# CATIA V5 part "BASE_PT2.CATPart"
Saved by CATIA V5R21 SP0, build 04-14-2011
Part number: BASE_PT2
Bounding box of the stored display mesh (mm): x -5 to 7, y -45.5 to 45.5, z -21.5 to 21.5
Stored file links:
  D:\MENA 3D\BISMARK\BASE_PT2.CATPart
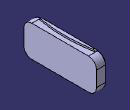
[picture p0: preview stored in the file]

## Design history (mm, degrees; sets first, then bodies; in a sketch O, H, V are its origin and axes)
Body1 (main body)
  Sketch1 on yz-plane, origin (0, 0, 0), H (0, 1, 0), V (0, 0, 1)
    line L1 (45.5, 9.5) -> (45.5, -9.5)
    line L2 (35.5, -19.5) -> (-35.5, -19.5)
    line L3 (-45.5, -9.5) -> (-45.5, 9.5)
    line L4 (-35.5, 19.5) -> (35.5, 19.5)
    arc A1 centre (-35.5, 9.5) radius 10 from (-45.5, 9.5) to (-35.5, 19.5) cw
    arc A2 centre (35.5, 9.5) radius 10 from (45.5, 9.5) to (35.5, 19.5) ccw
    arc A3 centre (-35.5, -9.5) radius 10 from (-35.5, -19.5) to (-45.5, -9.5) cw
    arc A4 centre (35.5, -9.5) radius 10 from (45.5, -9.5) to (35.5, -19.5) cw
    distance L3 L1 = 91
    distance L4 L2 = 39
    radius A1 = 10
    radius A2 = 10
    radius A3 = 10
    radius A4 = 10
    vertical: L1 V, L3 V
    horizontal: L2 H, L4 H
    equidistance: L1 L3 O, L2 L4 O
    tangency: A1 L3, A1 L4, A2 L1, A2 L4, A3 L2, A3 L3, A4 L1, A4 L2
  Pad1: profile Sketch1, direction (1, 0, 0), length 7, opposite side length 5
  Sketch2 on face of Pad1, origin (0, 0, 19.5), H (1, 0, 0), V (0, 1, 0)
    point P1 (-1.75, 35)
    line L1 (-1.75, 35) -> (-5, 35)
    line L2 (-5, 35) -> (-5, -35)
    line L3 (-5, -35) -> (-1.75, -35)
    point P4 (-1.75, -35)
    reference projected line E1 (-5, 35.5) -> (-5, -35.5) from edge [start face of Pad1 | face of Pad1 from Sketch1.L4]
    spline S1 through (-1.75, 35) (1.5, 0) (-1.75, -35)
    point P5 (-1.75, 35)
    point P6 (1.5, 0)
    point P7 (-1.75, -35)
    distance P6 L2 = 6.5
    distance L1 L3 = 70
    length L3 = 3.25
    length L1 = 3.25
    horizontal: L1 H, L3 H
    vertical: L2 V
    coincidence: L2 E1, P5 P1, P6 H, P7 P4
    symmetry: L3 L1 H
  Pad2: profile Sketch2, direction (0, 0, 1), length 2
  Chamfer1: length 2, angle 45, on edge [face of Pad2 from Sketch2.L3 | end face of Pad2]; edge [face of Pad2 from Sketch2.L1 | end face of Pad2]; edge [face of Pad2 | end face of Pad2]
  Sketch3 on face of Pad1, origin (0, 0, -19.5), H (1, 0, 0), V (0, -1, 0)
    point P1 (-5, 31.5)
    line L1 (-5, 31.5) -> (-5, -31.5)
    point P2 (-5, -31.5)
    spline S1 through (-5, 31.5) (-2, 0) (-5, -31.5)
    reference projected line E1 (-5, 35.5) -> (-5, -35.5) from edge [start face of Pad1 | face of Pad1 from Sketch1.L2]
    point P3 (-5, 31.5)
    point P4 (-2, 0)
    point P5 (-5, -31.5)
    distance P4 L1 = 3
    length L1 = 63
    vertical: L1 V
    coincidence: P3 P1, P4 H, P5 L1, P5 P2, L1 E1
    symmetry: P3 P5 H
  Pad3: profile Sketch3, direction (0, 0, -1), length 2
  Chamfer2: length 2, angle 45, on edge [face of Pad3 | end face of Pad3]
  Chamfer3: length 1, angle 45, on edge [face of Pad3 | face of Pad1 from Sketch1.A2]; edge [face of Pad3 | face of Pad1 from Sketch1.L1]; edge [face of Pad3 | face of Pad1 from Sketch1.A4]; edge [face of Pad3 | face of Pad1] (x2); edge [face of Pad3 | face of Pad1 from Sketch1.A3]; edge [face of Pad3 | face of Pad1 from Sketch1.L3]; edge [face of Pad3 | face of Pad1 from Sketch1.A1]
  Sketch4 on face of Pad3, origin (-5, 0, 0), H (0, -1, 0), V (0, 0, 1)
    circle A1 centre (0, 0) radius 14.5
    radius A1 = 14.5
  Pocket1: profile Sketch4, direction (1, 0, 0), length 10
  Chamfer4: length 2, angle 30, on edge [face of Pad3 | face of Pocket1 from Sketch4.A1]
